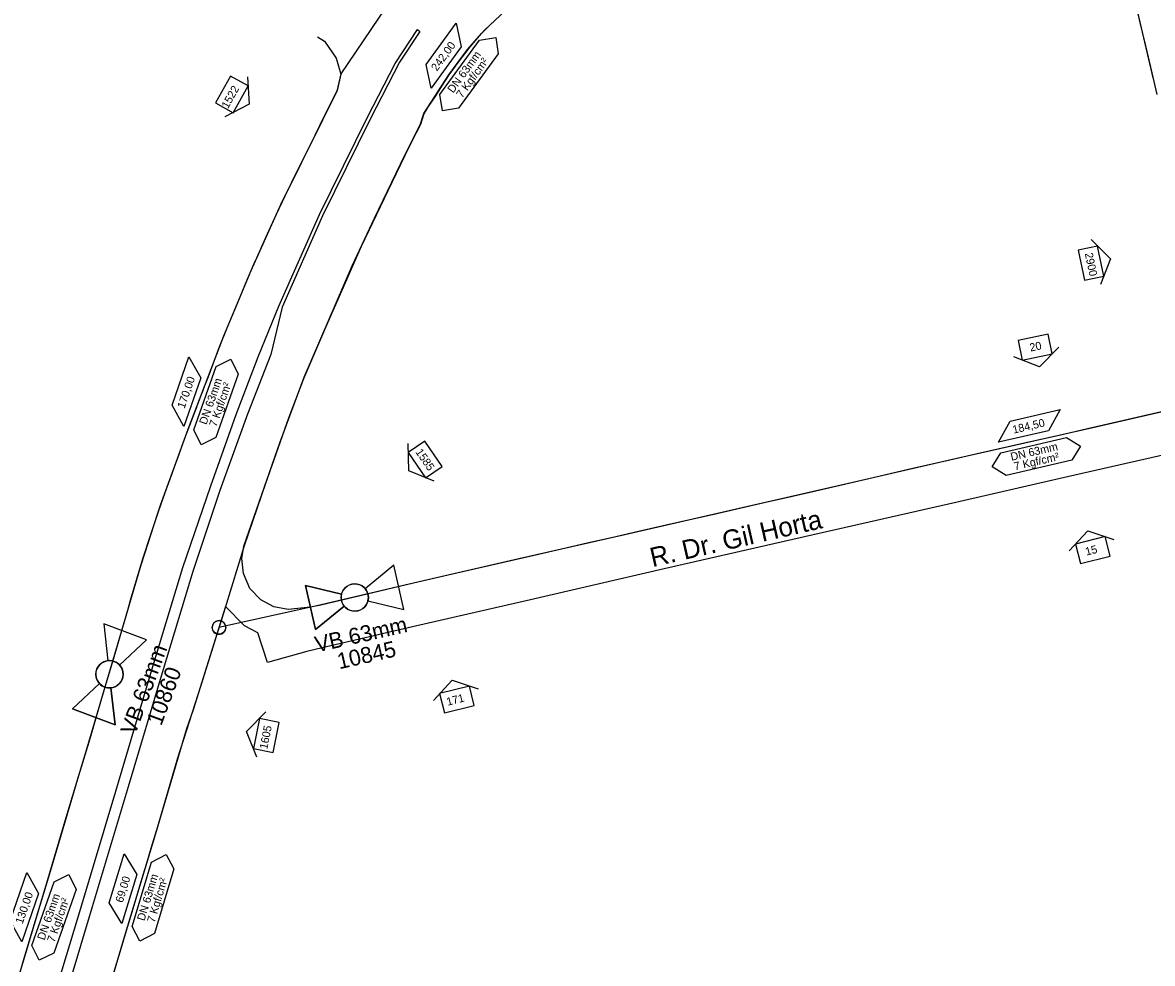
# Model space of a CAD drawing. Extents: x 656692 to 673945, y 7585994 to 7599066.
# Drawn here: x 670030 to 670453.7, y 7592467.1 to 7592820.1 of the extents above; entities that cross this region are included whole.
import ezdxf

# ---------------------------------------------------------------- set-up
doc = ezdxf.new("R2010")
doc.units = 0
for name, color, linetype in [('FORMATO', 7, 'Continuous'), ('LOGRADOURO', 7, 'Continuous'), ('LOGRADOURO_TEXTO', 7, 'Continuous'), ('NUM_REF', 7, 'Continuous'), ('SIMBOLO', 7, 'Continuous'), ('TEXTO', 7, 'Continuous'), ('TUBO_PEAD_GN_63', 7, 'Continuous'), ('VALVULA_PEAD_63', 7, 'Continuous')]:
    doc.layers.add(name, color=color, linetype=linetype)

# ---------------------------------------------------------------- blocks, each defined once
blk = doc.blocks.new('INTERLIGACAO_5')
at = {"layer": 'SIMBOLO'}
blk.add_circle((0, 0), 1.28, dxfattribs=at)
for start, end in [(0, 180), (180, 0)]:
    blk.add_arc((0, 0), 1.28, start, end, dxfattribs=at)
blk = doc.blocks.new('VALVULA_PEAD_DN_9')
at = {"layer": 'VALVULA_PEAD_63'}
for points in [[(-1.14, 0.57), (-4.25, 2.13), (-4.25, -2.13), (-1.14, -0.57)], [(-1.14, -0.57), (-4.25, -2.13), (-4.25, 2.13), (-1.14, 0.57)], [(1.14, -0.57), (4.25, -2.13), (4.25, 2.13), (1.14, 0.57)], [(1.14, -0.57), (4.25, -2.13), (4.25, 2.13), (1.14, 0.57)]]:
    blk.add_lwpolyline(points, dxfattribs=at)
blk.add_circle((0, 0), 1.28, dxfattribs=at)
for start, end in [(90, 270), (270, 90), (153.4349, 206.5651), (0, 26.5651), (333.4349, 0)]:
    blk.add_arc((0, 0), 1.28, start, end, dxfattribs=at)
blk = doc.blocks.new('NUM_REF_1')
at = {"layer": 'NUM_REF'}
blk.add_lwpolyline([(-4.3125, 0.9375), (0, 3.75), (4.3125, 0.9375)], dxfattribs=at)
blk.add_lwpolyline([(2.875, -1.875), (2.875, 1.875), (-2.875, 1.875), (-2.875, -1.875)], close=True, dxfattribs=at)

msp = doc.modelspace()

# ---------------------------------------------------------------- linework, layer by layer
at = {"layer": 'LOGRADOURO'}
for points in [[(670446.26, 7592832.11), (670454.04, 7592798.88)], [(670467.18, 7592676.33), (670431.32, 7592668.04), (670380.35, 7592656.51), (670341.34, 7592647.51), (670298.78, 7592637.72), (670255.81, 7592627.9), (670216.08, 7592618.85), (670178.72, 7592610.25), (670141.85, 7592601.56), (670138.02, 7592600.71), (670129.66, 7592599.81), (670124.28, 7592600.84), (670119.38, 7592603.5), (670115.23, 7592607.73), (670112.87, 7592613.4), (670112.25, 7592619.05), (670113, 7592623.69), (670126.48, 7592662.41), (670135.68, 7592687.06), (670153.61, 7592728.8), (670162, 7592746.7), (670173.4, 7592770.37), (670179.15, 7592781.72), (670180.48, 7592785.91), (670189.91, 7592800.5), (670196.9, 7592809.96), (670202.18, 7592816.12), (670203.28, 7592817.29), (670212.87, 7592826.27)], [(670039.1, 7592445.67), (670052.29, 7592489.11), (670064.98, 7592531.67), (670078.89, 7592578.43), (670090.15, 7592615.58), (670100.6, 7592646.22), (670110.07, 7592673.05), (670118.31, 7592694.69), (670126.14, 7592713.62), (670141.32, 7592748.01), (670159.37, 7592784.57), (670169.74, 7592804.73), (670178.08, 7592817.52), (670179.01, 7592816.75), (670171.43, 7592805.23), (670160.35, 7592783.83), (670142.46, 7592747.58), (670127.35, 7592713.3), (670123.1, 7592695.57), (670114.39, 7592673.11), (670104.05, 7592644.54), (670093.87, 7592614.19), (670082.79, 7592577.3), (670069.66, 7592533.29), (670056.17, 7592488.32), (670042.98, 7592444.37)], [(670140.67, 7592814.77), (670143.3, 7592813.13), (670147.59, 7592806.78), (670149.37, 7592800.72), (670148, 7592794.55), (670142.54, 7592783.47), (670126.74, 7592751.73), (670115.57, 7592726.99), (670105.38, 7592702.43), (670092.03, 7592667.42), (670081.67, 7592638.9), (670075.01, 7592618.77), (670070.43, 7592603.29), (670069.38, 7592599.53), (670054.1, 7592547.86), (670045.88, 7592520.43), (670039.4, 7592498.41), (670028.44, 7592462)], [(670472.46, 7592661.11), (670419.11, 7592649.03), (670379.97, 7592640.05), (670325.99, 7592627.79), (670270.57, 7592615.08), (670220.55, 7592603.56), (670176.22, 7592593.39), (670142.38, 7592585.49), (670136.63, 7592584.11), (670121.81, 7592580.03), (670118.22, 7592591.13), (670113.22, 7592593.7), (670106.14, 7592600.95), (670093.99, 7592562.19), (670091.55, 7592555.12), (670079.69, 7592515.28), (670068.09, 7592476.88), (670054.2, 7592429.79)]]:
    msp.add_lwpolyline(points, dxfattribs=at)
at = {"layer": 'SIMBOLO'}
for points in [[(670194.55, 7592811.03), (670183.24, 7592795.49), (670181.31, 7592804.31), (670192.62, 7592819.85)], [(670096.81, 7592686.74), (670090.48, 7592668.59), (670086.08, 7592676.48), (670092.41, 7592694.63)], [(670414.72, 7592666.93), (670395.99, 7592662.61), (670400.32, 7592670.54), (670419.05, 7592674.86)], [(670072.83, 7592500.46), (670067.27, 7592482.07), (670062.54, 7592489.76), (670068.1, 7592508.16)], [(670036.06, 7592493.33), (670029.74, 7592475.18), (670025.34, 7592483.07), (670031.67, 7592501.22)]]:
    msp.add_lwpolyline(points, close=True, dxfattribs=at)
for points in [[(670187.43, 7592787.01), (670186.46, 7592793.12), (670201.32, 7592813.54), (670207.44, 7592814.5), (670208.4, 7592808.39), (670193.54, 7592787.97), (670187.43, 7592787.01)], [(670096.94, 7592661.69), (670094.25, 7592667.26), (670102.56, 7592691.1), (670108.13, 7592693.79), (670110.83, 7592688.22), (670102.51, 7592664.38), (670096.94, 7592661.69)], [(670393.6, 7592653.46), (670396.87, 7592658.71), (670421.48, 7592664.39), (670426.72, 7592661.11), (670423.45, 7592655.86), (670398.84, 7592650.18), (670393.6, 7592653.46)], [(670074.01, 7592475.44), (670071.09, 7592480.89), (670078.4, 7592505.07), (670083.85, 7592507.99), (670086.77, 7592502.54), (670079.47, 7592478.36), (670074.01, 7592475.44)], [(670036.2, 7592468.28), (670033.51, 7592473.85), (670041.82, 7592497.69), (670047.39, 7592500.39), (670050.08, 7592494.81), (670041.77, 7592470.97), (670036.2, 7592468.28)]]:
    msp.add_lwpolyline(points, dxfattribs=at)
at = {"layer": 'TUBO_PEAD_GN_63'}
for points in [[(670421.92, 7592934.99), (670436.89, 7592872.25), (670440.61, 7592856.58), (670442.71, 7592846.91), (670444.61, 7592839.18), (670446.86, 7592829.64), (670448.9, 7592820.62), (670451.13, 7592811.35), (670453.49, 7592801.28), (670455.36, 7592793.06)], [(670169.24, 7592830.39), (670149.34, 7592800.82), (670147.92, 7592794.39), (670143.3, 7592785.23), (670137.77, 7592773.84), (670133.11, 7592764.7), (670128.34, 7592754.98), (670125.01, 7592747.87), (670121.15, 7592739.27), (670117.78, 7592731.75), (670117.14, 7592730.46), (670114.06, 7592723.38), (670110.59, 7592714.99), (670106.59, 7592705.41), (670103.51, 7592697.65), (670099.56, 7592687.22), (670098.6, 7592684.63), (670098.02, 7592683.14), (670097.45, 7592681.66), (670096.88, 7592680.14), (670096.59, 7592679.37), (670096.43, 7592678.94), (670096.34, 7592678.7), (670096.26, 7592678.5), (670096.19, 7592678.3), (670096.12, 7592678.11), (670096.05, 7592677.93), (670095.96, 7592677.69), (670095.89, 7592677.51), (670095.8, 7592677.29), (670095.72, 7592677.06), (670095.64, 7592676.87), (670095.54, 7592676.61), (670095.45, 7592676.38), (670095.36, 7592676.12), (670095.27, 7592675.89), (670095.19, 7592675.67), (670094.84, 7592674.77), (670092.6, 7592668.92), (670091.36, 7592665.63), (670090.29, 7592662.69), (670089.48, 7592660.51), (670088.49, 7592657.65), (670087.51, 7592654.98), (670086.13, 7592651.15), (670084.76, 7592647.4), (670083.41, 7592643.7), (670081.04, 7592636.95), (670079.29, 7592631.6), (670076.97, 7592624.63), (670074.34, 7592616.56), (670071.69, 7592607.57), (670067.5, 7592593.06), (670063.94, 7592581.12), (670060.13, 7592568.21), (670054.84, 7592550.07), (670050.94, 7592537.5), (670044.51, 7592515.51), (670039.65, 7592499.05), (670033.91, 7592480.2), (670030.53, 7592468.97), (670028.44, 7592461.89)], [(670209.11, 7592822.74), (670205.28, 7592819.17), (670201.26, 7592815.13), (670197.77, 7592810.99), (670196.18, 7592809.01), (670194.42, 7592806.65), (670192.24, 7592803.69), (670189.89, 7592800.46), (670187.13, 7592796.23), (670184.81, 7592792.6), (670181.92, 7592788.18), (670180.43, 7592785.86), (670179.19, 7592781.9), (670177.64, 7592778.72), (670175.27, 7592774.04), (670173.34, 7592770.23), (670168.44, 7592760.12), (670157.03, 7592736.07), (670143.67, 7592705.69), (670135.35, 7592686.42), (670129.73, 7592671.7), (670121.13, 7592647.14), (670113.08, 7592623.73), (670105.99, 7592600.49), (670096.85, 7592571.36), (670088.16, 7592544.1), (670080.56, 7592518.38), (670078.17, 7592510.24), (670076.31, 7592504.14), (670075.13, 7592500.18), (670073.71, 7592495.52), (670072.09, 7592490.1), (670070.56, 7592485.08), (670068.82, 7592479.26), (670067.2, 7592473.85), (670065.7, 7592468.83), (670064.25, 7592463.88)], [(670480.96, 7592679.5), (670442.92, 7592670.73), (670430.98, 7592667.98), (670418.68, 7592665.18), (670406.2, 7592662.42), (670389.11, 7592658.49), (670377.74, 7592655.94), (670363.86, 7592652.75), (670349.46, 7592649.42), (670331.24, 7592645.18), (670318.69, 7592642.31), (670308.12, 7592639.88), (670297.88, 7592637.52), (670288.75, 7592635.43), (670280.25, 7592633.49), (670271.41, 7592631.47), (670261.03, 7592629.13), (670250.88, 7592626.78), (670241.68, 7592624.7), (670232.16, 7592622.53), (670223.49, 7592620.53), (670191.26, 7592613.19), (670174.94, 7592609.41), (670160.57, 7592606.02), (670141.95, 7592601.6), (670138.06, 7592600.71), (670103.68, 7592593.13)]]:
    msp.add_lwpolyline(points, dxfattribs=at)

# ---------------------------------------------------------------- block references
at = {"layer": 'FORMATO'}
for p, xscale, yscale, rotation in [((670108.5, 7592793.12), 2, 2, -119.20534106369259), ((670430.66, 7592729.84), 2, 2, -78.08582592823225), ((670409.75, 7592698.31), 2, 2, -168.0566481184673), ((670181, 7592656.17), 2, 2, 124.6061821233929), ((670431.33, 7592622.15), 1.9999999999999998, 2.0000000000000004, 14.33307248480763), ((670192.92, 7592566.1), 1.9999999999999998, 2.0000000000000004, 14.33307248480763), ((670121.39, 7592552.61), 2, 2, 78.77481022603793)]:
    msp.add_blockref('NUM_REF_1', p, dxfattribs=dict(at, xscale=xscale, yscale=yscale, rotation=rotation))
at = {"layer": 'SIMBOLO', "xscale": 2, "yscale": 2, "rotation": 54.2694923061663}
msp.add_blockref('INTERLIGACAO_5', (670103.68, 7592593.13), dxfattribs=at)
at = {"layer": 'VALVULA_PEAD_63'}
for p, xscale, yscale, rotation in [((670154.58, 7592604.38), 3.9999999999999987, 3.9999999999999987, 12.793654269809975), ((670062.61, 7592575.56), 3.999999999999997, 3.999999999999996, 69.69495140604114)]:
    msp.add_blockref('VALVULA_PEAD_DN_9', p, dxfattribs=dict(at, xscale=xscale, yscale=yscale, rotation=rotation))

# ---------------------------------------------------------------- texts
for s, height, rotation, p in [('1522', 3, 60.7947, (670107.03, 7592787.57)), ('2900', 3, 281.9142, (670428.33, 7592733.43)), ('20', 3, 11.9434, (670407.99, 7592696.63)), ('1585', 3, 304.6062, (670177.2, 7592658.96)), ('15', 3, 14.3331, (670428.95, 7592620.07)), ('VB 63mm', 6, 12.7937, (670140.4, 7592583.73)), ('10845', 6, 12.7937, (670148.75, 7592577.42)), ('VB 63mm', 6, 69.695, (670072.17, 7592552.4)), ('10860', 6, 69.695, (670082.01, 7592555.96)), ('171', 3, 14.3331, (670189.41, 7592563.74)), ('1605', 3, 78.7748, (670121.78, 7592547.28))]:
    msp.add_text(s, height=height, rotation=rotation).set_placement(p)
at = {"layer": 'LOGRADOURO_TEXTO'}
msp.add_text('R. Dr. Gil Horta', height=7.2, rotation=12.9047, dxfattribs=at).set_placement((670266.22, 7592615.77))
at = {"layer": 'TEXTO'}
for s, rotation, p in [('242,00', 53.9463, (670185.37, 7592801.61)), ('DN 63mm', 53.9463, (670191.48, 7592793.42)), ('7 Kgf/cm²', 53.9463, (670194.82, 7592791.56)), ('170,00', 70.7854, (670090.75, 7592675.06)), ('DN 63mm', 70.7854, (670098.96, 7592669)), ('7 Kgf/cm²', 70.7854, (670102.7, 7592668.19)), ('184,50', 12.9963, (670401.61, 7592665.83)), ('DN 63mm', 12.9963, (670400.86, 7592655.65)), ('7 Kgf/cm²', 12.9963, (670402.17, 7592652.05)), ('69,00', 73.1868, (670067.6, 7592489.66)), ('DN 63mm', 73.1868, (670075.72, 7592482.83)), ('7 Kgf/cm²', 73.1868, (670079.5, 7592482.18)), ('130,00', 70.7854, (670030.01, 7592481.66)), ('DN 63mm', 70.7854, (670038.22, 7592475.59)), ('7 Kgf/cm²', 70.7854, (670041.96, 7592474.78))]:
    msp.add_text(s, height=3, rotation=rotation, dxfattribs=at).set_placement(p)

doc.saveas('drawing.dxf')
